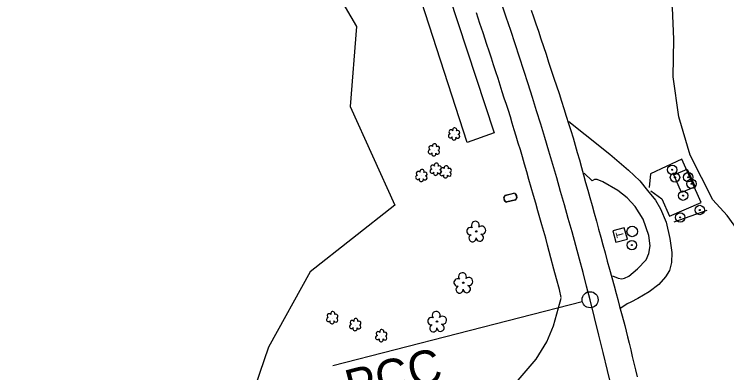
# Model space of a CAD drawing. Extents: x 471894 to 476235, y 503501 to 507878.
# Drawn here: x 474193.2 to 474525.3, y 504923.2 to 505090.4 of the extents above; entities that cross this region are included whole.
import ezdxf

# ---------------------------------------------------------------- set-up
doc = ezdxf.new("R2010")
doc.units = 0
for name, color, linetype in [('Exist Horizontal Alignment', 7, 'Continuous'), ('Exist Horizontal Alignment Direction Label', 7, 'Continuous'), ('Exist Other Culture Area Outline', 7, 'Continuous'), ('Exist Other Culture Fence Line', 7, 'Continuous'), ('Exist Other Culture Gate', 7, 'Continuous'), ('Exist Other Culture Sign', 7, 'Continuous'), ('Exist Other Culture Sign Post CELL', 7, 'Continuous'), ('Exist Roads EOP', 7, 'Continuous'), ('Exist Roads EOP Other', 7, 'Continuous'), ('Exist Roads Soil', 7, 'Continuous'), ('Exist Utilities Other Located Object CELL', 7, 'Continuous'), ('Exist Utilities Other Pole CELL', 7, 'Continuous'), ('Exist Utilities Telephone Pedestal CELL', 7, 'Continuous'), ('Exist Utilities Water Meter CELL', 7, 'Continuous'), ('Exist Vegetation Shrub CELL', 7, 'Continuous'), ('Exist Vegetation Tree CELL', 7, 'Continuous'), ('Exist Vegetation Woods Line', 7, 'Continuous')]:
    doc.layers.add(name, color=color, linetype=linetype)

msp = doc.modelspace()

# ---------------------------------------------------------------- linework, layer by layer
at = {"layer": 'Exist Horizontal Alignment'}
msp.add_line((474457.95, 504956.33), (474341.69, 504926.49), dxfattribs=at)
msp.add_circle((474461.59, 504957.26), 3.75, dxfattribs=at)
for centre, radius, start, end in [((472660.82, 504495.17), 1859.11, 14.39186, 20.84556), ((472536.78, 504463.34), 1987.17, 358.7675, 14.39186)]:
    msp.add_arc(centre, radius, start, end, dxfattribs=at)
at = {"layer": 'Exist Other Culture Area Outline'}
msp.add_lwpolyline([(474506.88, 505018.23), (474510.5, 505009.95), (474504.23, 505007.2), (474500.61, 505015.49)], close=True, dxfattribs=at)
at = {"layer": 'Exist Other Culture Fence Line'}
msp.add_lwpolyline([(474495.03, 505004.26), (474498.67, 504996.19), (474513.41, 505002.57), (474504.42, 505022.89), (474489.82, 505016)], dxfattribs=at)
at = {"layer": 'Exist Other Culture Gate'}
for p, q in [((474489.82, 505016), (474489.14, 505009.62)), ((474489.84, 505008.05), (474495.03, 505004.26))]:
    msp.add_line(p, q, dxfattribs=at)
at = {"layer": 'Exist Other Culture Sign'}
msp.add_line((474516.02, 504998.86), (474500.58, 504993.49), dxfattribs=at)
at = {"layer": 'Exist Other Culture Sign Post CELL'}
for centre, radius in [((474512.73, 504999.11), 2.18), ((474512.73, 504999.11), 0.24), ((474503.63, 504995.63), 2.18), ((474503.63, 504995.63), 0.24), ((474481.07, 504982.76), 2.18), ((474481.07, 504982.76), 0.24)]:
    msp.add_circle(centre, radius, dxfattribs=at)
at = {"layer": 'Exist Roads EOP'}
for points in [[(474434.19, 505092.37), (474435.27, 505089.19), (474436.38, 505085.9), (474437.52, 505082.51), (474438.68, 505079), (474439.86, 505075.42), (474441.06, 505071.79), (474442.28, 505068.1), (474443.52, 505064.37), (474444.76, 505060.64), (474445.96, 505056.98), (474447.14, 505053.39), (474448.28, 505049.86), (474449.4, 505046.38), (474450.49, 505042.93), (474451.57, 505039.52), (474452.61, 505036.14), (474453.64, 505032.76), (474454.65, 505029.35), (474455.64, 505025.92), (474456.61, 505022.45), (474457.58, 505018.96), (474458.55, 505015.46), (474459.53, 505011.95), (474460.51, 505008.43), (474461.5, 505004.87), (474462.5, 505001.28), (474463.51, 504997.64), (474464.53, 504993.95), (474465.55, 504990.24), (474466.57, 504986.52), (474467.58, 504982.8), (474468.6, 504979.06), (474469.62, 504975.3), (474470.65, 504971.49), (474471.7, 504967.64), (474472.75, 504963.74), (474473.71, 504960.19), (474474.47, 504957.39), (474475.37, 504954.05), (474476.53, 504949.74), (474477.73, 504945.22), (474479.07, 504939.9), (474479.78, 504936.97), (474480.51, 504933.93), (474481.26, 504930.84), (474482.01, 504927.7), (474482.78, 504924.51), (474483.55, 504921.3)], [(474448.15, 504958.35), (474447.26, 504962.03), (474445.95, 504966.96), (474444.77, 504971.5), (474443.36, 504976.84), (474442.58, 504979.73), (474441.75, 504982.77), (474440.89, 504985.9), (474440.01, 504989.06), (474439.12, 504992.26), (474438.21, 504995.49), (474437.27, 504998.8), (474436.28, 505002.25), (474435.25, 505005.85), (474434.17, 505009.58), (474433.08, 505013.33), (474432.04, 505016.96), (474431.02, 505020.46), (474430.04, 505023.85), (474429.09, 505027.14), (474428.14, 505030.35), (474427.2, 505033.49), (474426.27, 505036.55), (474425.35, 505039.56), (474424.42, 505042.53), (474423.49, 505045.47), (474422.56, 505048.38), (474421.62, 505051.3), (474420.66, 505054.28), (474419.68, 505057.32), (474418.68, 505060.43), (474417.67, 505063.58), (474416.63, 505066.75), (474415.58, 505069.96), (474414.51, 505073.2), (474413.48, 505076.31), (474411.71, 505081.67), (474410.25, 505086.11), (474408.61, 505091.02)]]:
    msp.add_lwpolyline(points, dxfattribs=at)
at = {"layer": 'Exist Roads EOP Other'}
for points in [[(474446.91, 504953.55), (474448.09, 504957.99)], [(474345.92, 504867.53), (474348.98, 504867.32), (474351.93, 504868.46), (474369.71, 504876.99), (474388.35, 504888.21), (474413.53, 504907.31), (474428.05, 504919.81), (474436.49, 504929.49), (474441.42, 504937.69), (474444.56, 504945.08), (474446.91, 504953.55)]]:
    msp.add_lwpolyline(points, dxfattribs=at)
at = {"layer": 'Exist Roads Soil'}
for points in [[(474562.13, 504900.47), (474558.05, 504918.25), (474552.88, 504939.87), (474549.4, 504953.17), (474547.37, 504960.35), (474536.82, 504980.92), (474525.48, 504996.52), (474518.84, 505003.91), (474508.25, 505024.72), (474502.99, 505042.57), (474500.31, 505061.24), (474500.56, 505078.84), (474500.07, 505093.34), (474498.05, 505101.43)], [(474451.62, 505040.42), (474459.32, 505034.28), (474470.76, 505025.2), (474479.57, 505017.74), (474484.8, 505012.69), (474488.4, 505008.22), (474492.11, 505003.63), (474494.48, 504999.59), (474497.07, 504993.47), (474498.76, 504985.86), (474499.67, 504979.33), (474499.49, 504974.66), (474498.53, 504970.97), (474496.7, 504967.97), (474493.71, 504964.38), (474489.1, 504960.95), (474483.79, 504957.87), (474480.64, 504956.12), (474478.87, 504955.37), (474475.93, 504953.34)], [(474472.11, 504968.41), (474474.66, 504967.26), (474476.44, 504967.01), (474477.59, 504967.35), (474479.59, 504968.19), (474483.67, 504971.65), (474487.78, 504975.94), (474488.9, 504978.76), (474489.57, 504982.37), (474489.05, 504987.17), (474486.3, 504994.78), (474482.61, 505000.73), (474478.88, 505004.79), (474474.45, 505008.14), (474467.47, 505012.25), (474464.87, 505013.32), (474463.68, 505013.39), (474462.49, 505012.79), (474458.87, 505016.33)]]:
    msp.add_lwpolyline(points, dxfattribs=at)
at = {"layer": 'Exist Utilities Other Located Object CELL'}
for centre, radius in [((474499.9, 505017.86), 2.18), ((474501.17, 505014.32), 2.18), ((474499.9, 505017.86), 0.24), ((474507.34, 505014.4), 2.18), ((474501.17, 505014.32), 0.24), ((474508.84, 505011.35), 2.18), ((474507.34, 505014.4), 0.24), ((474508.84, 505011.35), 0.24), ((474504.93, 505005.8), 2.18), ((474504.93, 505005.8), 0.24)]:
    msp.add_circle(centre, radius, dxfattribs=at)
at = {"layer": 'Exist Utilities Other Pole CELL'}
msp.add_circle((474481.22, 504989.11), 2.46, dxfattribs=at)
at = {"layer": 'Exist Utilities Telephone Pedestal CELL'}
msp.add_line((474475.53, 504987.38), (474475.53, 504987.38), dxfattribs=at)
msp.add_lwpolyline([(474478.96, 504985.46), (474477.54, 504990.87), (474472.13, 504989.46), (474473.55, 504984.04), (474478.96, 504985.46)], dxfattribs=at)
at = {"layer": 'Exist Utilities Water Meter CELL'}
msp.add_line((474424.42, 505004.88), (474424.42, 505004.88), dxfattribs=at)
for points in [[(474422.02, 505006.03), (474425.97, 505007.03)], [(474422.06, 505005.89), (474426.01, 505006.9)], [(474426.78, 505003.87), (474422.8, 505002.86)], [(474426.81, 505003.73), (474422.84, 505002.72)]]:
    msp.add_lwpolyline(points, dxfattribs=at)
for centre, radius, start, end in [((474423.15, 505004.55), 1.86, 127.4189, 260.2203), ((474423.16, 505004.56), 1.73, 129.5418, 258.0232), ((474425.67, 505005.2), 1.86, 307.8892, 80.5492), ((474425.68, 505005.2), 1.73, 309.368, 79.1137)]:
    msp.add_arc(centre, radius, start, end, dxfattribs=at)
at = {"layer": 'Exist Vegetation Shrub CELL'}
for p, q in [((474398.27, 505034.39), (474398.27, 505034.39)), ((474388.88, 505026.99), (474388.88, 505026.99)), ((474383.04, 505015.01), (474383.04, 505015.01)), ((474389.72, 505017.93), (474389.72, 505017.93)), ((474394.33, 505016.73), (474394.33, 505016.73)), ((474341.44, 504948.71), (474341.44, 504948.71)), ((474352.17, 504945.47), (474352.17, 504945.47)), ((474364.32, 504940.32), (474364.32, 504940.32))]:
    msp.add_line(p, q, dxfattribs=at)
for centre, radius, start, end in [((474396.79, 505035.52), 0.968, 35.8908, 245.4216), ((474398.5, 505036.43), 0.99, 334.8391, 200.4717), ((474399.95, 505035.26), 0.929, 284.4567, 126.0861), ((474396.47, 505033.69), 0.955, 95.1099, 327.9534), ((474398.15, 505032.71), 0.984, 151.2797, 21.387), ((474399.91, 505033.46), 0.937, 204.9913, 73.4601), ((474387.4, 505028.11), 0.968, 35.8908, 245.4216), ((474389.11, 505029.03), 0.99, 334.8391, 200.4717), ((474390.55, 505027.86), 0.929, 284.4567, 126.0861), ((474387.08, 505026.28), 0.955, 95.1099, 327.9534), ((474388.75, 505025.3), 0.984, 151.2797, 21.387), ((474390.52, 505026.06), 0.937, 204.9913, 73.4601), ((474388.24, 505019.06), 0.968, 35.8908, 245.4216), ((474389.95, 505019.97), 0.99, 334.8391, 200.4717), ((474391.4, 505018.8), 0.929, 284.4567, 126.0861), ((474392.85, 505017.86), 0.968, 35.8908, 245.4216), ((474394.56, 505018.77), 0.99, 334.8391, 200.4717), ((474396.01, 505017.6), 0.929, 284.4567, 126.0861), ((474381.24, 505014.31), 0.955, 95.1099, 327.9534), ((474381.56, 505016.14), 0.968, 35.8908, 245.4216), ((474383.27, 505017.05), 0.99, 334.8391, 200.4717), ((474384.68, 505014.08), 0.937, 204.9913, 73.4601), ((474384.72, 505015.88), 0.929, 284.4567, 126.0861), ((474387.92, 505017.23), 0.955, 95.1099, 327.9534), ((474389.6, 505016.25), 0.984, 151.2797, 21.387), ((474391.36, 505017), 0.937, 204.9913, 73.4601), ((474392.53, 505016.03), 0.955, 95.1099, 327.9534), ((474394.21, 505015.05), 0.984, 151.2797, 21.387), ((474395.97, 505015.81), 0.937, 204.9913, 73.4601), ((474382.92, 505013.33), 0.984, 151.2797, 21.387), ((474339.64, 504948), 0.955, 95.1099, 327.9534), ((474339.96, 504949.83), 0.968, 35.8908, 245.4216), ((474341.67, 504950.75), 0.99, 334.8391, 200.4717), ((474343.08, 504947.78), 0.937, 204.9913, 73.4601), ((474343.11, 504949.58), 0.929, 284.4567, 126.0861), ((474341.31, 504947.02), 0.984, 151.2797, 21.387), ((474350.37, 504944.76), 0.955, 95.1099, 327.9534), ((474350.69, 504946.6), 0.968, 35.8908, 245.4216), ((474352.4, 504947.51), 0.99, 334.8391, 200.4717), ((474353.81, 504944.54), 0.937, 204.9913, 73.4601), ((474353.84, 504946.34), 0.929, 284.4567, 126.0861), ((474352.04, 504943.79), 0.984, 151.2797, 21.387), ((474362.84, 504941.44), 0.968, 35.8908, 245.4216), ((474364.55, 504942.36), 0.99, 334.8391, 200.4717), ((474365.99, 504941.18), 0.929, 284.4567, 126.0861), ((474362.52, 504939.61), 0.955, 95.1099, 327.9534), ((474364.19, 504938.63), 0.984, 151.2797, 21.387), ((474365.96, 504939.39), 0.937, 204.9913, 73.4601)]:
    msp.add_arc(centre, radius, start, end, dxfattribs=at)
at = {"layer": 'Exist Vegetation Tree CELL'}
for p, q in [((474408.5, 504989.11), (474408.5, 504989.11)), ((474402.47, 504965.15), (474402.47, 504965.15)), ((474390.23, 504947.1), (474390.23, 504947.1))]:
    msp.add_line(p, q, dxfattribs=at)
for centre in [(474408.5, 504989.11), (474402.47, 504965.15), (474390.23, 504947.1)]:
    msp.add_circle(centre, 0.326, dxfattribs=at)
for centre, radius, start, end in [((474408.12, 504991.98), 1.86, 330.1651, 219.7134), ((474405.89, 504989.26), 1.73, 62.6636, 279.3457), ((474411.05, 504989.69), 1.9, 257.1011, 134.1999), ((474406.8, 504985.99), 1.69, 111.5671, 6.231), ((474410.17, 504986.21), 1.7, 181.2822, 74.56), ((474402.09, 504968.03), 1.86, 330.1651, 219.7134), ((474399.87, 504965.31), 1.73, 62.6636, 279.3457), ((474405.02, 504965.74), 1.9, 257.1011, 134.1999), ((474400.77, 504962.03), 1.69, 111.5671, 6.231), ((474404.15, 504962.25), 1.7, 181.2822, 74.56), ((474387.63, 504947.25), 1.73, 62.6636, 279.3457), ((474389.85, 504949.97), 1.86, 330.1651, 219.7134), ((474392.78, 504947.68), 1.9, 257.1011, 134.1999), ((474388.53, 504943.97), 1.69, 111.5671, 6.231), ((474391.9, 504944.2), 1.7, 181.2822, 74.56)]:
    msp.add_arc(centre, radius, start, end, dxfattribs=at)
at = {"layer": 'Exist Vegetation Woods Line'}
for points in [[(474333.63, 505261.37), (474391.56, 505112.22), (474416.96, 505035.11), (474404.23, 505030.66), (474383.08, 505096.38), (474361.36, 505165.52), (474344.78, 505214.38), (474331, 505244.92), (474311.95, 505251.22), (474316.11, 505264.81), (474333.63, 505261.37)], [(474039.74, 505231.39), (474070.64, 505227.57), (474100.38, 505210.48), (474145.85, 505197.49), (474221.93, 505186.17), (474248.45, 505176.22), (474277.09, 505162.04), (474333.09, 505118.27), (474352.71, 505084.66), (474349.72, 505047.44), (474370.59, 505001.39), (474331.17, 504970.24), (474311.76, 504935.08), (474292.73, 504879.6), (474286.83, 504842.4), (474281, 504828.7), (474253.76, 504800.95), (474212.37, 504772.4), (474185.95, 504758.02), (474194.18, 504746.5), (474168.72, 504709.09), (474147.17, 504667.02), (474132.12, 504653.24), (474125.76, 504660.6)]]:
    msp.add_lwpolyline(points, dxfattribs=at)

# ---------------------------------------------------------------- texts
at = {"layer": 'Exist Horizontal Alignment'}
msp.add_text('PCC', height=16, rotation=14.3919, dxfattribs=at).set_placement((474349.99, 504908.42))
at = {"layer": 'Exist Horizontal Alignment Direction Label'}
msp.add_text('N 20%%d 50\' 44" W', height=16, rotation=133.8986, dxfattribs=at).set_placement((474575.34, 505072.11))
at = {"layer": 'Exist Utilities Telephone Pedestal CELL'}
msp.add_text('T', height=3.42, rotation=104.6687, dxfattribs=at).set_placement((474477.48, 504986.72))

doc.saveas('drawing.dxf')
